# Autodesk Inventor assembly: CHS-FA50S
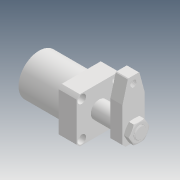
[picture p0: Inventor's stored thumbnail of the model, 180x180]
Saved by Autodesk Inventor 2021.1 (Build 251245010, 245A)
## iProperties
Created: 2019-04
Part Number: CHS-FA50S
Description: STEP AP203
Document SubType Name: Assembly
Designer: user
Title: chs-fa50s_asm.STEP
Revision Number: ÈÎºÎ
Sending System: SolidWorks 2017
Preprocessor: SwSTEP 2.0
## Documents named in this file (5)
- D:\Vault_2016\Projekty\Clamptek\Hydraulic\CHS\CHS-50\Inventor\CHS-FA50S\CHS-FA50S.iam
- D:\Vault_2016\Projekty\Clamptek\Hydraulic\CHS\CHS-50\Inventor\CHS-FA50S\CHS-FA50BT_1.ipt
- D:\Vault_2016\Projekty\Clamptek\Hydraulic\CHS\CHS-50\Inventor\CHS-FA50S\CHS-50SHSG_1.ipt
- D:\Vault_2016\Projekty\Clamptek\Hydraulic\CHS\CHS-50\Inventor\CHS-FA50S\CHS-50SYB_1.ipt
- D:\Vault_2016\Projekty\Clamptek\Hydraulic\CHS\CHS-50\Inventor\CHS-FA50S\M20LM_1.ipt
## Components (4 placed, 4 different names)
1. CHS-FA50BT_1_1
2. CHS-50SHSG_1_2
3. CHS-50SYB_1_3
4. M20LM_1_4
